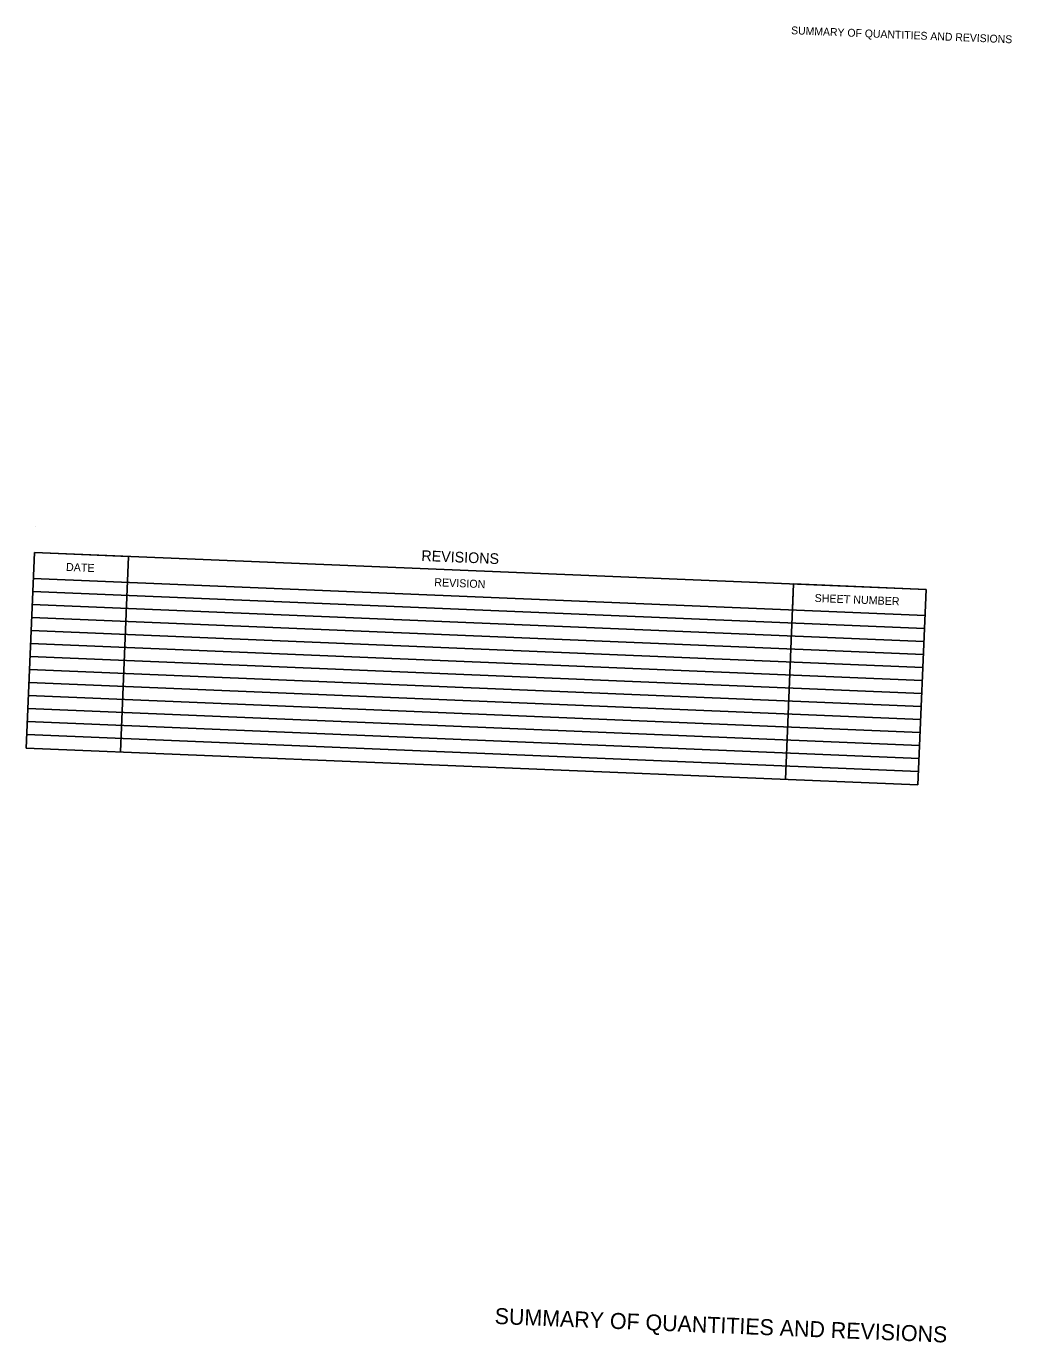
# Model space of a CAD drawing. Extents: x 1164179 to 1171425, y 1655958 to 1657208.
# Drawn here: x 1170686 to 1171425, y 1655958 to 1656945 of the extents above; entities that cross this region are included whole.
import ezdxf

# ---------------------------------------------------------------- set-up
doc = ezdxf.new("R2010")
doc.units = 0
for name, color, linetype in [('Default', 7, 'Continuous'), ('R_Border Prem', 7, 'Continuous'), ('R_Grid', 7, 'Continuous')]:
    doc.layers.add(name, color=color, linetype=linetype)

msp = doc.modelspace()

# ---------------------------------------------------------------- linework, layer by layer
at = {"layer": 'Default'}
for p, q in [((1170692.73, 1656570.18), (1170692.73, 1656570.18)), ((1170685.85, 1656404.09), (1170691.92, 1656550.7)), ((1170691.92, 1656550.7), (1171360.69, 1656523.03)), ((1170691.92, 1656550.7), (1170762.55, 1656547.78)), ((1170756.48, 1656401.16), (1170762.55, 1656547.78)), ((1170691.11, 1656531.22), (1171359.88, 1656503.55)), ((1171255.26, 1656380.53), (1171261.32, 1656527.14)), ((1171260.51, 1656507.66), (1171261.32, 1656527.14)), ((1171261.32, 1656527.14), (1171360.69, 1656523.03)), ((1170690.71, 1656521.47), (1171359.48, 1656493.81)), ((1171354.62, 1656376.42), (1171360.69, 1656523.03)), ((1171354.62, 1656376.42), (1171360.69, 1656523.03)), ((1170690.31, 1656511.73), (1171359.07, 1656484.07)), ((1170689.9, 1656501.99), (1171358.67, 1656474.32)), ((1170689.5, 1656492.25), (1171358.27, 1656464.58)), ((1170689.1, 1656482.51), (1171357.86, 1656454.84)), ((1170688.7, 1656472.77), (1171357.46, 1656445.1)), ((1170688.29, 1656463.02), (1171357.06, 1656435.36)), ((1170687.89, 1656453.28), (1171356.66, 1656425.62)), ((1170687.49, 1656443.54), (1171356.25, 1656415.87)), ((1170687.08, 1656433.8), (1171355.85, 1656406.13)), ((1170686.68, 1656424.06), (1171355.45, 1656396.39)), ((1170686.28, 1656414.32), (1171355.04, 1656386.65)), ((1170685.85, 1656404.09), (1171354.62, 1656376.42))]:
    msp.add_line(p, q, dxfattribs=at)

# ---------------------------------------------------------------- texts
for s, height, p in [('REVISIONS', 8, (1170982.03, 1656544.45)), ('DATE', 6, (1170715.51, 1656536.96)), ('REVISION', 6, (1170991.73, 1656525.54)), ('SHEET NUMBER', 6, (1171276.99, 1656513.73))]:
    msp.add_text(s, height=height, rotation=357.63112, dxfattribs=at).set_placement(p)
at = {"layer": 'R_Border Prem'}
msp.add_text('SUMMARY OF QUANTITIES AND REVISIONS', height=12, rotation=357.63112, dxfattribs=at).set_placement((1171036.94, 1655972.32))
at = {"layer": 'R_Grid'}
msp.add_text('SUMMARY OF QUANTITIES AND REVISIONS', height=5.862, rotation=357.63112, dxfattribs=at).set_placement((1171259.37, 1656939.42))

doc.saveas('drawing.dxf')
